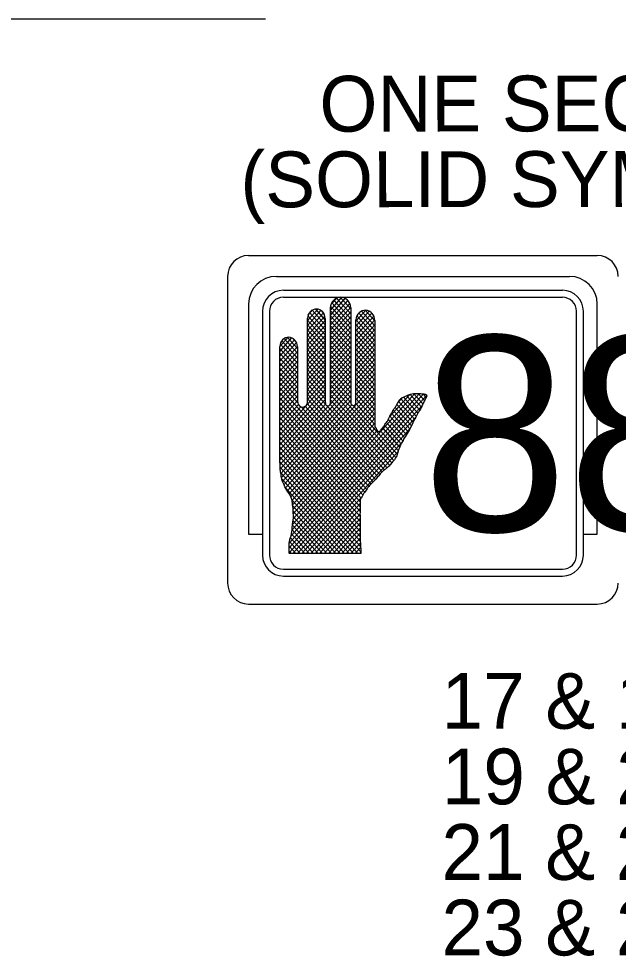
# Model space of a CAD drawing. Extents: x -15.7 to 19.3, y -1.4 to 10.8.
# Drawn here: x 7.725 to 8.441, y 9.39 to 10.511 of the extents above; entities that cross this region are included whole.
import ezdxf

# ---------------------------------------------------------------- set-up
doc = ezdxf.new("R2010")
doc.units = 0
doc.layers.add('T_Drafting', color=7, linetype='Continuous')
doc.layers.add('T_Notes', color=7, linetype='Continuous')

msp = doc.modelspace()

# ---------------------------------------------------------------- linework, layer by layer
at = {"layer": 'T_Drafting'}
for p, q in [((7.9992, 10.2276), (8.4158, 10.2276)), ((7.9742, 10.2026), (7.9742, 9.8359)), ((8.0325, 10.2026), (8.3825, 10.2026)), ((8.0408, 10.1859), (8.3742, 10.1859)), ((8.0408, 10.1776), (8.3742, 10.1776)), ((8.0969, 10.1623), (8.1106, 10.1776)), ((8.0978, 10.1692), (8.1045, 10.1766)), ((8.1043, 10.1766), (8.1213, 10.1578)), ((8.1087, 10.1776), (8.1213, 10.1637)), ((7.9992, 10.1693), (7.9992, 9.8943)), ((8.0969, 10.1564), (8.1146, 10.1762)), ((8.0969, 10.1506), (8.1177, 10.1737)), ((8.0969, 10.1447), (8.12, 10.1703)), ((8.0969, 10.1388), (8.1212, 10.1658)), ((8.0971, 10.1669), (8.1213, 10.1401)), ((8.0987, 10.1711), (8.1213, 10.146)), ((8.1011, 10.1743), (8.1213, 10.1519)), ((8.1165, 10.1749), (8.1188, 10.1723)), ((8.4158, 9.8943), (8.4158, 10.1693)), ((8.0158, 10.1609), (8.0158, 9.8693)), ((8.0242, 10.1609), (8.0242, 9.8693)), ((8.0696, 10.1497), (8.0819, 10.1633)), ((8.0696, 10.1438), (8.0857, 10.1617)), ((8.0696, 10.1379), (8.0886, 10.159)), ((8.0696, 10.132), (8.0904, 10.1551)), ((8.0702, 10.1556), (8.0908, 10.1327)), ((8.0705, 10.1566), (8.0757, 10.1624)), ((8.0721, 10.1594), (8.0908, 10.1386)), ((8.075, 10.162), (8.0908, 10.1445)), ((8.0791, 10.1634), (8.0908, 10.1504)), ((8.0862, 10.1614), (8.089, 10.1583)), ((8.097, 10.0509), (8.0969, 10.1647)), ((8.0969, 10.1613), (8.1213, 10.1342)), ((8.0969, 10.1329), (8.1213, 10.16)), ((8.0969, 10.1554), (8.1213, 10.1283)), ((8.0969, 10.127), (8.1213, 10.1541)), ((8.1213, 10.165), (8.1214, 10.0521)), ((8.1274, 10.1491), (8.1392, 10.1621)), ((8.1274, 10.1432), (8.1434, 10.161)), ((8.1274, 10.1373), (8.1466, 10.1586)), ((8.1274, 10.1314), (8.1489, 10.1552)), ((8.1287, 10.1554), (8.1501, 10.1316)), ((8.131, 10.1588), (8.1501, 10.1375)), ((8.1342, 10.1611), (8.1501, 10.1434)), ((8.1385, 10.1622), (8.1501, 10.1493)), ((8.3908, 9.8693), (8.3908, 10.1609)), ((8.3992, 9.8693), (8.3992, 10.1609)), ((8.0697, 10.053), (8.0696, 10.1525)), ((8.0696, 10.1504), (8.0908, 10.1268)), ((8.0696, 10.1261), (8.0908, 10.1497)), ((8.0696, 10.1445), (8.0908, 10.1209)), ((8.0696, 10.1202), (8.0908, 10.1438)), ((8.0908, 10.1522), (8.0909, 10.0515)), ((8.0969, 10.1495), (8.1213, 10.1224)), ((8.0969, 10.1211), (8.1213, 10.1482)), ((8.0969, 10.1436), (8.1213, 10.1165)), ((8.1274, 10.1509), (8.1501, 10.1257)), ((8.1274, 10.1255), (8.15, 10.1507)), ((8.1275, 10.0515), (8.1274, 10.1506)), ((8.1274, 10.1451), (8.1501, 10.1198)), ((8.1274, 10.1197), (8.1501, 10.1448)), ((8.1501, 10.1499), (8.1502, 10.0222)), ((8.0696, 10.1386), (8.0908, 10.115)), ((8.0696, 10.1144), (8.0908, 10.1379)), ((8.0696, 10.1327), (8.0909, 10.1091)), ((8.0696, 10.1085), (8.0908, 10.132)), ((8.0969, 10.1152), (8.1213, 10.1423)), ((8.0969, 10.1377), (8.1213, 10.1106)), ((8.0969, 10.1318), (8.1213, 10.1047)), ((8.097, 10.1094), (8.1213, 10.1364)), ((8.1274, 10.1392), (8.1501, 10.1139)), ((8.1274, 10.1138), (8.1501, 10.1389)), ((8.1274, 10.1333), (8.1501, 10.108)), ((8.1274, 10.1079), (8.1501, 10.1331)), ((8.0365, 10.1187), (8.0464, 10.1298)), ((8.0365, 10.1129), (8.051, 10.129)), ((8.0365, 10.107), (8.0542, 10.1267)), ((8.0365, 10.1011), (8.0565, 10.1234)), ((8.037, 10.1218), (8.0577, 10.0988)), ((8.0389, 10.1256), (8.0577, 10.1047)), ((8.0418, 10.1282), (8.0577, 10.1106)), ((8.0458, 10.1297), (8.0577, 10.1165)), ((8.0525, 10.1281), (8.0562, 10.124)), ((8.0696, 10.1268), (8.0909, 10.1032)), ((8.0696, 10.1026), (8.0908, 10.1261)), ((8.0696, 10.1209), (8.0909, 10.0973)), ((8.0969, 10.1259), (8.1214, 10.0988)), ((8.097, 10.1035), (8.1213, 10.1305)), ((8.097, 10.0976), (8.1213, 10.1247)), ((8.1274, 10.1274), (8.1501, 10.1021)), ((8.1274, 10.102), (8.1501, 10.1272)), ((8.1274, 10.1215), (8.1501, 10.0962)), ((8.1275, 10.0961), (8.1501, 10.1213)), ((8.0366, 9.9814), (8.0364, 10.1188)), ((8.0365, 10.0952), (8.0577, 10.1187)), ((8.0365, 10.1165), (8.0577, 10.0929)), ((8.0365, 10.0893), (8.0577, 10.1129)), ((8.0365, 10.1106), (8.0577, 10.087)), ((8.0577, 10.1185), (8.0577, 10.053)), ((8.0696, 10.0967), (8.0908, 10.1203)), ((8.0696, 10.115), (8.0909, 10.0914)), ((8.0697, 10.0908), (8.0908, 10.1144)), ((8.0969, 10.12), (8.1214, 10.0929)), ((8.0969, 10.1141), (8.1214, 10.087)), ((8.097, 10.0917), (8.1213, 10.1188)), ((8.097, 10.0858), (8.1213, 10.1129)), ((8.1274, 10.1156), (8.1501, 10.0903)), ((8.1274, 10.1097), (8.1501, 10.0844)), ((8.1275, 10.0902), (8.1501, 10.1154)), ((8.1275, 10.0843), (8.1501, 10.1095)), ((8.0365, 10.0834), (8.0577, 10.107)), ((8.0365, 10.1047), (8.0577, 10.0811)), ((8.0365, 10.0775), (8.0577, 10.1011)), ((8.0365, 10.0988), (8.0577, 10.0752)), ((8.0696, 10.1091), (8.0909, 10.0855)), ((8.0696, 10.1032), (8.0909, 10.0796)), ((8.0697, 10.0849), (8.0909, 10.1085)), ((8.0697, 10.079), (8.0909, 10.1026)), ((8.097, 10.1082), (8.1214, 10.0811)), ((8.097, 10.0799), (8.1213, 10.107)), ((8.097, 10.1023), (8.1214, 10.0752)), ((8.097, 10.0741), (8.1214, 10.1011)), ((8.1274, 10.1038), (8.1502, 10.0785)), ((8.1275, 10.0785), (8.1501, 10.1036)), ((8.0365, 10.0717), (8.0577, 10.0952)), ((8.0365, 10.0929), (8.0577, 10.0693)), ((8.0365, 10.0658), (8.0577, 10.0893)), ((8.0365, 10.087), (8.0577, 10.0634)), ((8.0696, 10.0973), (8.0909, 10.0737)), ((8.0697, 10.0732), (8.0909, 10.0967)), ((8.0697, 10.0914), (8.0909, 10.0678)), ((8.0697, 10.0673), (8.0909, 10.0908)), ((8.097, 10.0964), (8.1214, 10.0693)), ((8.097, 10.0682), (8.1214, 10.0952)), ((8.097, 10.0905), (8.1214, 10.0634)), ((8.097, 10.0623), (8.1214, 10.0893)), ((8.1275, 10.0979), (8.1502, 10.0726)), ((8.1275, 10.0726), (8.1501, 10.0977)), ((8.1275, 10.092), (8.1502, 10.0667)), ((8.1275, 10.0667), (8.1501, 10.0919)), ((8.0365, 10.0599), (8.0577, 10.0834)), ((8.0365, 10.0811), (8.0577, 10.0575)), ((8.0365, 10.054), (8.0577, 10.0776)), ((8.0697, 10.0855), (8.0909, 10.0619)), ((8.0697, 10.0614), (8.0909, 10.0849)), ((8.0697, 10.0796), (8.0909, 10.056)), ((8.0697, 10.0555), (8.0909, 10.0791)), ((8.097, 10.0846), (8.1214, 10.0575)), ((8.097, 10.0564), (8.1214, 10.0835)), ((8.097, 10.0787), (8.1213, 10.0517)), ((8.097, 10.0504), (8.1214, 10.0776)), ((8.1275, 10.0861), (8.1502, 10.0609)), ((8.1275, 10.0608), (8.1501, 10.086)), ((8.1275, 10.0802), (8.1502, 10.055)), ((8.1275, 10.0549), (8.1502, 10.0801)), ((8.0365, 10.0752), (8.0579, 10.0514)), ((8.0365, 10.0481), (8.0577, 10.0717)), ((8.0365, 10.0693), (8.1428, 9.9512)), ((8.0365, 10.0422), (8.0577, 10.0658)), ((8.0366, 10.0128), (8.0909, 10.0732)), ((8.0366, 10.0069), (8.0909, 10.0673)), ((8.0368, 9.9777), (8.1214, 10.0717)), ((8.037, 9.972), (8.1214, 10.0658)), ((8.0415, 9.9534), (8.1502, 10.0742)), ((8.0435, 9.9498), (8.1502, 10.0683)), ((8.0697, 10.0737), (8.0912, 10.0498)), ((8.0697, 10.0678), (8.1588, 9.9688)), ((8.097, 10.0728), (8.1752, 9.9859)), ((8.097, 10.0669), (8.1729, 9.9826)), ((8.1275, 10.0743), (8.1502, 10.0491)), ((8.1275, 10.0684), (8.1502, 10.0432)), ((8.0365, 10.0634), (8.1403, 9.948)), ((8.0365, 10.0363), (8.0577, 10.0599)), ((8.0365, 10.0575), (8.1381, 9.9446)), ((8.0365, 10.0305), (8.0577, 10.054)), ((8.0366, 10.001), (8.0909, 10.0614)), ((8.0366, 9.9951), (8.0909, 10.0555)), ((8.0378, 9.967), (8.1214, 10.0599)), ((8.0386, 9.9621), (8.1214, 10.054)), ((8.0456, 9.9463), (8.1502, 10.0624)), ((8.0477, 9.9427), (8.1502, 10.0565)), ((8.0479, 9.878), (8.212, 10.0604)), ((8.048, 9.8841), (8.2081, 10.062)), ((8.0498, 9.892), (8.2033, 10.0625)), ((8.051, 9.8992), (8.198, 10.0625)), ((8.0697, 10.0619), (8.1562, 9.9658)), ((8.0697, 10.056), (8.1536, 9.9628)), ((8.097, 10.061), (8.1704, 9.9795)), ((8.097, 10.0551), (8.1678, 9.9765)), ((8.1275, 10.0625), (8.1502, 10.0373)), ((8.1275, 10.0566), (8.1502, 10.0314)), ((8.1675, 10.0346), (8.1918, 10.0615)), ((8.1775, 10.0516), (8.1832, 10.0579)), ((8.181, 10.0561), (8.1996, 10.0354)), ((8.1843, 10.0583), (8.2016, 10.039)), ((8.188, 10.0601), (8.2038, 10.0426)), ((8.1919, 10.0616), (8.2058, 10.0462)), ((8.1964, 10.0625), (8.2075, 10.0502)), ((8.2017, 10.0625), (8.2094, 10.054)), ((8.2074, 10.0621), (8.2112, 10.0578)), ((8.0365, 10.0516), (8.1357, 9.9414)), ((8.0365, 10.0457), (8.1338, 9.9376)), ((8.0366, 9.9893), (8.0911, 10.0499)), ((8.0366, 10.0246), (8.0588, 10.0493)), ((8.0366, 9.9834), (8.0946, 10.0479)), ((8.0366, 10.0187), (8.0618, 10.0468)), ((8.0397, 9.9574), (8.1224, 10.0492)), ((8.0479, 9.8722), (8.2069, 10.0488)), ((8.0497, 9.939), (8.1502, 10.0507)), ((8.0513, 9.9349), (8.1502, 10.0448)), ((8.0622, 10.0466), (8.1455, 9.9541)), ((8.0668, 10.0474), (8.1482, 9.957)), ((8.0693, 10.0506), (8.1509, 9.9599)), ((8.0927, 10.0481), (8.1616, 9.9715)), ((8.0967, 10.0496), (8.1648, 9.9739)), ((8.1243, 10.0484), (8.1768, 9.99)), ((8.1274, 10.0508), (8.1502, 10.0255)), ((8.1719, 10.0426), (8.1919, 10.0204)), ((8.1743, 10.0459), (8.1939, 10.0241)), ((8.1763, 10.0495), (8.1958, 10.0278)), ((8.1785, 10.053), (8.1977, 10.0316)), ((8.0365, 10.0398), (8.1325, 9.9332)), ((8.0365, 10.0339), (8.1326, 9.9271)), ((8.0519, 9.9296), (8.1502, 10.0389)), ((8.0523, 9.8712), (8.1989, 10.0341)), ((8.0524, 9.9243), (8.1502, 10.033)), ((8.1661, 10.0314), (8.1855, 10.0098)), ((8.1679, 10.0353), (8.1877, 10.0132)), ((8.1699, 10.039), (8.1899, 10.0167)), ((8.0366, 10.028), (8.1324, 9.9215)), ((8.0366, 10.0221), (8.1324, 9.9156)), ((8.0526, 9.9128), (8.151, 10.0221)), ((8.0527, 9.9188), (8.1502, 10.0271)), ((8.0576, 9.8712), (8.192, 10.0205)), ((8.1591, 10.0215), (8.1797, 9.9986)), ((8.1616, 10.0246), (8.1815, 10.0024)), ((8.1638, 10.028), (8.1835, 10.0061)), ((8.0366, 10.0162), (8.1327, 9.9094)), ((8.0366, 10.0103), (8.1327, 9.9035)), ((8.0517, 9.9059), (8.1529, 10.0183)), ((8.1566, 10.0183), (8.1781, 9.9944)), ((8.0366, 10.0044), (8.1327, 9.8976)), ((8.0366, 9.9985), (8.1327, 9.8917)), ((8.0629, 9.8712), (8.1823, 10.0038)), ((8.0366, 9.9926), (8.1328, 9.8857)), ((8.0366, 9.9867), (8.133, 9.8796)), ((8.0682, 9.8712), (8.1775, 9.9927)), ((8.0366, 9.9808), (8.1333, 9.8733)), ((8.0368, 9.9746), (8.1299, 9.8713)), ((8.0377, 9.9678), (8.1246, 9.8713)), ((8.0389, 9.9606), (8.1193, 9.8713)), ((8.0441, 9.9489), (8.114, 9.8713)), ((8.0512, 9.9351), (8.1087, 9.8713)), ((8.0735, 9.8712), (8.1347, 9.9392)), ((8.0788, 9.8712), (8.1326, 9.9309)), ((8.052, 9.9283), (8.1034, 9.8712)), ((8.0525, 9.9218), (8.0981, 9.8712)), ((8.0841, 9.8712), (8.1325, 9.925)), ((8.0895, 9.8712), (8.1324, 9.9189)), ((8.0524, 9.9102), (8.0875, 9.8712)), ((8.0527, 9.9157), (8.0928, 9.8712)), ((8.0948, 9.8712), (8.1325, 9.9132)), ((8.051, 9.8999), (8.0769, 9.8712)), ((8.0516, 9.9052), (8.0822, 9.8712)), ((8.1001, 9.8712), (8.1327, 9.9075)), ((8.1054, 9.8712), (8.1327, 9.9016)), ((7.9992, 9.8943), (8.0158, 9.8943)), ((8.0481, 9.8855), (8.061, 9.8712)), ((8.0492, 9.8902), (8.0663, 9.8712)), ((8.0504, 9.8947), (8.0716, 9.8712)), ((8.1107, 9.8713), (8.1327, 9.8957)), ((8.116, 9.8713), (8.1327, 9.8898)), ((8.3992, 9.8943), (8.4158, 9.8943)), ((8.0479, 9.8799), (8.0557, 9.8712)), ((8.0479, 9.874), (8.0504, 9.8712)), ((8.1213, 9.8713), (8.1328, 9.884)), ((8.1266, 9.8713), (8.133, 9.8784)), ((8.0483, 9.8712), (8.0479, 9.8717)), ((8.133, 9.8713), (8.0483, 9.8712)), ((8.1319, 9.8713), (8.1333, 9.8728)), ((8.1333, 9.8712), (8.133, 9.8713)), ((8.0408, 9.8526), (8.3742, 9.8526)), ((8.0408, 9.8443), (8.3742, 9.8443)), ((7.9992, 9.8109), (8.4158, 9.8109))]:
    msp.add_line(p, q, dxfattribs=at)
for centre, radius, start, end in [((7.9992, 10.2026), 0.025, 90, 180), ((8.4158, 10.2026), 0.025, 0, 90), ((8.0325, 10.1693), 0.0333, 90, 180), ((8.3825, 10.1693), 0.0333, 0, 90), ((8.0408, 10.1609), 0.025, 90, 180), ((8.0408, 10.1609), 0.0167, 90, 180), ((8.3742, 10.1609), 0.025, 0, 90), ((8.3742, 10.1609), 0.0167, 0, 90), ((8.0408, 9.8693), 0.025, 180, 270), ((8.0408, 9.8693), 0.0167, 180, 270), ((8.3742, 9.8693), 0.025, 270, 0), ((8.3742, 9.8693), 0.0167, 270, 0), ((7.9992, 9.8359), 0.025, 180, 270), ((8.4158, 9.8359), 0.025, 270, 0)]:
    msp.add_arc(centre, radius, start, end, dxfattribs=at)
for centre, major_axis, start_param, end_param in [((8.1091, 10.1641), (0, -0.0136), 1.640121, 4.665593), ((8.0802, 10.1517), (0, -0.0118), 1.618611, 4.644084), ((8.1387, 10.1495), (0, -0.0126), 1.597842, 4.623315), ((8.0471, 10.118), (0, -0.0118), 1.618611, 4.644084), ((8.0637, 10.053), (0, -0.00664), 4.713646, 7.855239), ((8.094, 10.0512), (0, -0.0034), 4.633755, 7.775348), ((8.1244, 10.0518), (0, -0.00345), 4.624552, 7.766145)]:
    msp.add_ellipse(centre, major_axis=major_axis, ratio=0.9, start_param=start_param, end_param=end_param, dxfattribs=at)
for points in [[(8.1502, 10.0223), (8.1511, 10.022), (8.1522, 10.0194), (8.1537, 10.0175), (8.1546, 10.0172), (8.156, 10.0175), (8.1569, 10.0188), (8.1596, 10.022), (8.1616, 10.0247), (8.1628, 10.0266), (8.1639, 10.0282), (8.166, 10.0312), (8.1672, 10.0338), (8.1689, 10.0374), (8.1701, 10.0393), (8.1721, 10.0429), (8.1745, 10.0462), (8.1762, 10.0494), (8.1783, 10.0527), (8.1801, 10.055), (8.1827, 10.0576), (8.1859, 10.0589), (8.1877, 10.0599), (8.1903, 10.0609), (8.1926, 10.0619), (8.1962, 10.0625), (8.1991, 10.0625), (8.2029, 10.0626), (8.2064, 10.0622), (8.2105, 10.0616), (8.2117, 10.0609), (8.212, 10.0599), (8.2102, 10.0557), (8.2091, 10.0534), (8.2079, 10.0511), (8.2067, 10.0485), (8.2061, 10.0469), (8.2038, 10.0426), (8.2003, 10.0368), (8.1956, 10.0273), (8.1898, 10.0165), (8.1851, 10.009), (8.1824, 10.0041), (8.1801, 9.9996), (8.1787, 9.9959), (8.178, 9.9941), (8.1754, 9.9862), (8.1713, 9.9807), (8.1681, 9.9768), (8.1634, 9.9728), (8.1605, 9.9705), (8.1529, 9.962), (8.1461, 9.9549), (8.1418, 9.95), (8.1379, 9.9444), (8.136, 9.942), (8.1344, 9.9386), (8.1327, 9.9353), (8.1327, 9.9281), (8.1324, 9.9217), (8.1324, 9.9158), (8.1327, 9.908), (8.1327, 9.9005), (8.1327, 9.8884), (8.133, 9.8787), (8.1333, 9.8751), (8.1333, 9.8725), (8.1333, 9.8712)], [(8.0479, 9.8717), (8.0479, 9.8769), (8.0481, 9.8857), (8.0505, 9.8949), (8.0516, 9.9053), (8.0525, 9.9112), (8.0525, 9.9226), (8.0516, 9.932), (8.0507, 9.9369), (8.0463, 9.945), (8.0416, 9.9532), (8.039, 9.9601), (8.0378, 9.9672), (8.0369, 9.9728), (8.0369, 9.9763), (8.0366, 9.9814)]]:
    msp.add_spline(points, degree=3, dxfattribs=at)
at = {"layer": 'T_Notes'}
msp.add_line((6.3829, 10.5106), (8.0193, 10.5106), dxfattribs=at)

# ---------------------------------------------------------------- texts
at = {"layer": 'T_Drafting'}
for s, height, p in [('ONE SECTION', 0.066667, (8.0839, 10.3756)), ('(SOLID SYMBOL)', 0.066667, (7.9895, 10.2851)), ('88', 0.23333, (8.2069, 9.8979))]:
    msp.add_text(s, height=height, rotation=0.072, dxfattribs=at).set_placement(p)
at = {"layer": 'T_Notes'}
for s, p in [('17 & 18', (8.2298, 9.6618)), ('19 & 20', (8.2301, 9.5714)), ('21 & 22', (8.2297, 9.4811)), ('23 & 24', (8.2297, 9.3908))]:
    msp.add_text(s, height=0.06667, dxfattribs=at).set_placement(p)

doc.saveas('drawing.dxf')
